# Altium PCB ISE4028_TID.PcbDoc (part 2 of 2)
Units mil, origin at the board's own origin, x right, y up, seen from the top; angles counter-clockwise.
Board outline 4000 x 3450 mil, 4 copper layers (Layer 1 - Top Layer, Layer 2 - GND, Layer 3 - PWR, Layer 4 - Bottom Layer), stack 61.434 mil thick; 151 components, 89 nets, 421 pads, 328 vias.
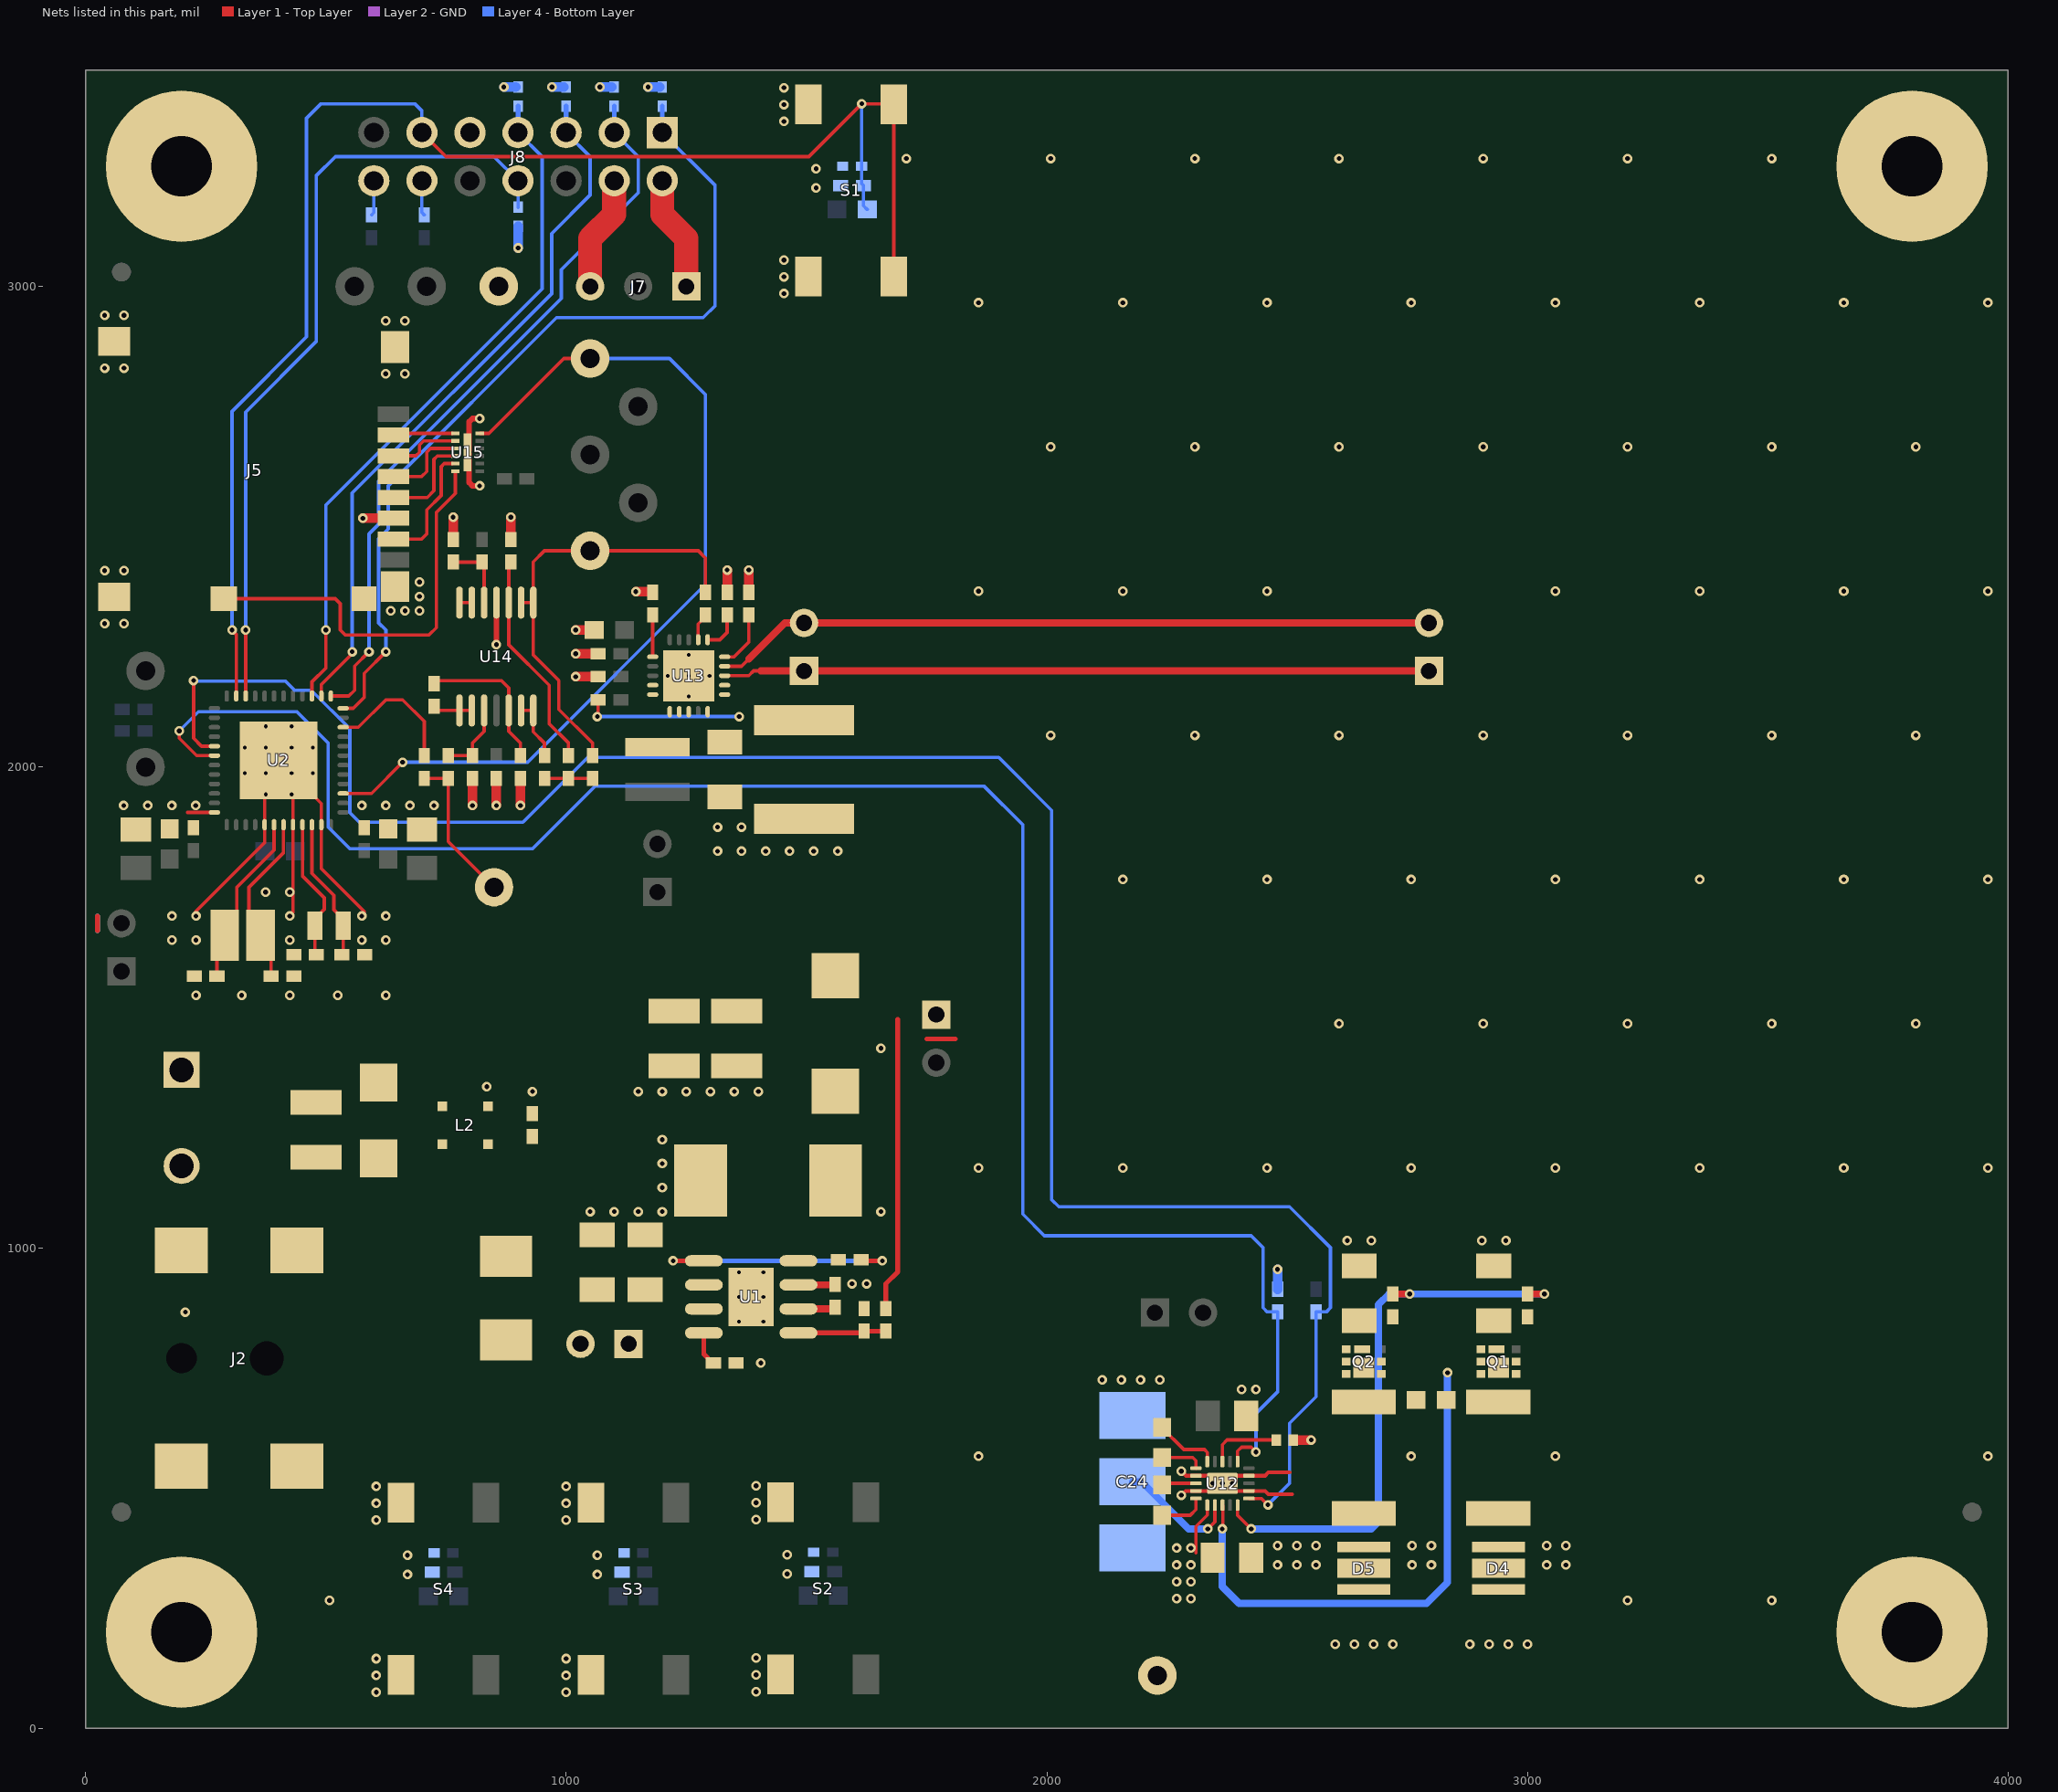
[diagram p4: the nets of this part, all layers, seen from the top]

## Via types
v1: diameter 20, hole 10, Layer 1 - Top Layer to Layer 4 - Bottom Layer, tented both sides, 305 vias
v2: diameter 19.68, hole 7.87, Layer 1 - Top Layer to Layer 4 - Bottom Layer, 17 vias
v3: diameter 19.68, hole 7.87, Layer 1 - Top Layer to Layer 4 - Bottom Layer, tented top, 6 vias

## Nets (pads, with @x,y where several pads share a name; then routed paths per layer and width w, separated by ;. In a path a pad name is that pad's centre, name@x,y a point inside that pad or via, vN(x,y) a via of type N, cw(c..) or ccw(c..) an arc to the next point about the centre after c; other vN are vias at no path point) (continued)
GND: C2.2 C3.2 C5.2 C6.2 C7.2 C8.2 C9.1 C10.1 C11.2 C12.1 C13.1 C14.2 C15.2 C16.2 C17.2 C18.2 C19.2 C20.2 C21.2 C22.2 C23.2 C24.2 C25.2 C28.2 C29.1 C30.2 C31.2 C32.2 C33.1 C35.2 C37.2 C38.2 D3.2 D6.1 H1.1 H2.1 H3.1 H4.1 J5.6 J5.9 J5.10 J5.12 J5.13 J5.14 J8.9 L2.3 R1.2 R3.1 R12.1 R20.1 R21.1 R26.1 R28.1 R29.1 R31.1 S1.3 S1.4 S2.3 S2.4 S3.3 S3.4 S4.3 S4.4 TP1.1 TP2.1 U1.7 U1.9 U2.36 U2.41 U2.44 U2.47 U2.49 U3.2 U4.2 U5.2 U6.2 U7.2 U8.2 U9.2 U10.2 U11.2 U12.7 U12.9 U12.17 U12.19 U12.21 U13.4 U13.5 U13.6 U13.21 U14.11 U15.13 | length 2699.3
  Layer 1 - Top Layer w7: 212.88,1905.71 U2.36@268.43,1905.71 ; v1@230,1695 230,1700 372.76,1842.76 U2.41@372.76,1880.12 372.76,1940.29 v2(375.58,1943.11) ; v2(429,1943.11) 431.82,1940.29 U2.44@431.82,1880.12 v1@431.82,1696.82 ; U2.49@470,1945 490.87,1924.13 U2.47@490.87,1880.12 490.87,1788.57 580,1699.44 v1@580,1695 ; U12.21@2349.62,493.98 v1(2365.37,509.72) ; U12.21@2349.62,525.47 v1(2365.37,509.72) ; U12.21@2381.12,493.98 v1(2365.37,509.72) ; U12.21@2381.12,525.47 v1(2365.37,509.72)
  Layer 1 - Top Layer w8: v1(2280,485) 2288.98,493.98 U12.19@2310.25,493.98 U12.21@2349.62,493.98 ; v1(2280,535) 2289.53,525.47 U12.17@2310.25,525.47 U12.21@2349.62,525.47 ; U12.21@2381.12,493.98 U12.7@2420.49,493.98 2454.02,493.98 2461,487 2510,487 ; U12.21@2381.12,525.47 U12.9@2420.49,525.47 2454.02,525.47 2461,532.45 2505,532.45
  Layer 1 - Top Layer w10: 25,1660 25,1690 ; 1750,1434.5 1810,1434.5
  Layer 1 - Top Layer w12: v1(820,2585) 805,2585 798.23,2591.77 798.23,2651.77 U15.13@795,2655 798.23,2658.23 798.23,2718.23 805,2725 v1(820,2725) ; v1(855,2255) U14.11@855,2342.2
  Layer 1 - Top Layer w15: U1.7@1483.39,922.73 1559.11,922.73 C8.2@1560,923.62
  Layer 1 - Top Layer w20: v1(577.36,2517.64) J5.6@640.75,2517.64 ; R31.1@765,2473.63 v1(765,2520) ; v1(805,1920) R29.1@805,1976.38 ; v1(855,1920) C28.2@855,1976.38 ; C31.2@885,2473.63 v1(885,2520) ; v1(905,1920) C32.2@905,1976.38 ; v1(1020,2187.98) R26.1@1066.38,2187.98 ; v1(1020,2235.96) C29.1@1066.38,2235.96 ; v1(1020,2285) C38.2@1058.5,2285 ; v1(1145,2365) 1178.62,2365 C33.1@1180,2363.62 ; C35.2@1335,2363.62 v1(1335,2410) ; R28.1@1380,2363.62 v1(1380,2410) ; D6.1@2515,600 v1(2550,600)
  Layer 2 - GND w10: 25,1660 25,1690
  Layer 4 - Bottom Layer w10: 25,1660 25,1690
  Layer 4 - Bottom Layer w20: v1(870.32,3414.69) U11.2@895,3414.69 ; v1(900,3080) U7.2@900,3125.31 ; v1(970.32,3414.69) U10.2@995,3414.69 ; v1(1070.32,3414.69) U8.2@1095,3414.69 ; v1(1170.32,3414.69) U6.2@1195,3414.69 ; R12.1@2480,913.62 v1(2480,955)
  other v1: 605,75 1000,75 1395,76.3 605,110 1000,110 1395,111.3 605,145 1000,145 1395,146.3 2600,175 2640,175 2680,175 2720,175 2880,175 2920,175 2960,175 3000,175 508,266 3208,266 3508,266 670,320 1065,320 1460,321.3 2480,340 2520,340 2560,340 2760,340 2800,340 3040,340 3080,340 670,360 1065,360 1460,361.3 2480,380 2520,380 2560,380 2760,380 2800,380 3040,380 3080,380 605,433.26 1000,433.27 1395,434.57 605,468.26 1000,468.27 1395,469.57 605,503.26 1000,503.27 1395,504.57 2345,510 2385.83,509.72 1858,566 2758,566 3058,566 3958,566 2405,705 2435,705 2115,725 2155,725 2195,725 2235,725 1405,760 208,866 1595,925 1625,925 2625,1015 2675,1015 2905,1015 2955,1015 1050,1075 1100,1075 1150,1075 1200,1075 1655,1075 1200,1125 1858,1166 2158,1166 2458,1166 2758,1166 3058,1166 3358,1166 3658,1166 3958,1166 1200,1175 1200,1225 930,1325 1150,1325 1200,1325 1250,1325 1300,1325 1350,1325 1400,1325 835,1335 1655,1415 2608,1466 2908,1466 3208,1466 3508,1466 3808,1466 230,1525 325,1525 425,1525 525,1525 625,1525 180,1640 230,1640 425,1640 575,1640 625,1640 180,1690 230,1690 425,1690 575,1690 625,1690 375,1740 425,1740 2158,1766 2458,1766 2758,1766 3058,1766 3358,1766 3658,1766 3958,1766 1315,1825 1365,1825 1415,1825 1465,1825 1515,1825 1565,1825 1315,1875 1365,1875 79.58,1920 129.58,1920 179.58,1920 229.58,1920 575,1920 625,1920 675,1920 725,1920 2008,2066 2308,2066 2608,2066 2908,2066 3208,2066 3508,2066 3808,2066 40,2298.5 80,2298.5 635,2325 665,2325 695,2325 695,2355 1858,2366 2158,2366 2458,2366 3058,2366 3358,2366 3658,2366 3958,2366 695,2385 40,2408.5 80,2408.5 2008,2666 2308,2666 2608,2666 2908,2666 3208,2666 3508,2666 3808,2666 624.65,2818.19 664.65,2818.19 40,2830 80,2830 624.65,2928.19 664.65,2928.19 40,2940 80,2940 1858,2966 2158,2966 2458,2966 2758,2966 3058,2966 3358,2966 3658,2966 3958,2966 1453.05,2985 1453.05,3020 1453.05,3055 1520,3205 1520,3245 1708,3266 2008,3266 2308,3266 2608,3266 2908,3266 3208,3266 3508,3266 1453.05,3343.27 1453.05,3378.27 1453.05,3413.27
  other v2: 331.42,1987.26 375.58,1987.26 429,1987.26 473.16,1987.26 331.42,2040.69 375.58,2040.69 429,2040.69 473.16,2040.69 375.58,2084.84 429,2084.84 1255,2146.69 1211.69,2190 1255,2190 1298.31,2190 1255,2233.31
  other v3: 1359.37,846.55 1410.55,846.55 1359.37,897.73 1410.55,897.73 1359.37,948.91 1410.55,948.91
HFXIN: C21.1 U2.42 Y2.1 | length 308.8
  Layer 1 - Top Layer w7: C21.1@273.62,1565 273.62,1634.02 Y2.1@289.6,1650 ; Y2.1@315,1695 315,1750 392.45,1827.45 U2.42@392.45,1880.12
HFXOUT: C22.1 U2.43 Y2.2 | length 314.1
  Layer 1 - Top Layer w7: Y2.2@340,1690 340,1750 412.13,1822.13 U2.43@412.13,1880.12 ; Y2.2@364.4,1650 386.38,1628.02 C22.1@386.38,1565
LFXIN: C17.1 U2.45 Y1.1 | length 273.2
  Layer 1 - Top Layer w7: U2.45@451.5,1880.12 451.5,1773.5 497,1728 497,1704 Y1.1@485,1692 ; Y1.1@477.47,1670 477.47,1613.15 C17.1@480.62,1610
LFXOUT: C18.1 U2.46 Y1.2 | length 272.5
  Layer 1 - Top Layer w7: U2.46@471.19,1880.12 471.19,1778.81 517,1733 517,1703 527,1693 Y1.2@528,1693 ; C18.1@533.38,1610 536.53,1613.15 Y1.2@536.53,1670
LM3550_FB: R18.1 R19.1 U12.5 | length 1208.1
  Layer 1 - Top Layer w7: U12.5@2396.87,464.45 2396.87,443.13 v1(2425,415)
  Layer 1 - Top Layer w15: R19.1@2720,903.62 v1(2755,903.62) ; R18.1@3000,903.62 v1(3035,903.62)
  Layer 4 - Bottom Layer w15: v1(2425,415) 2675,415 2690,430 2690,881.65 2711.97,903.62 v1(2755,903.62) v1(3035,903.62)
MSP_PWM: R27.1 R32.2 TP12.1 | length 315.7
  Layer 1 - Top Layer w7: R32.2@705,1976.38 R27.1@755,1976.38 755,1845 TP12.1@850,1750
MSP_PWM_FLT: C34.1 C36.2 TP11.1 U14.8 U14.9 | length 925.2
  Layer 1 - Top Layer w7: U14.9@906.18,2342.2 U14.8@931.77,2342.2 ; C34.1@1055,2023.63 1055,2050 985,2120 985,2180 931.77,2233.23 U14.8@931.77,2342.2 ; C36.2@1290,2363.62 1290,2435 1275,2450 TP11.1@1050,2450 955,2450 931.77,2426.77 U14.8@931.77,2342.2
NCS_SD: TP5.1 U2.3 U15.12 | length 1893.9
  Layer 1 - Top Layer w7: U2.3@536.15,1945.08 595.08,1945.08 v1(660,2010) ; U15.12@820.59,2694.37 839.37,2694.37 995,2850 TP5.1@1050,2850
  Layer 4 - Bottom Layer w7: v1(660,2010) 920,2010 1290,2380 1290,2775 1215,2850 TP5.1@1050,2850
NEOC: R9.1 U2.29 U12.6 | length 4359.2
  Layer 1 - Top Layer w7: v1(225,2180) 225,2060 241.5,2043.5 U2.29@268.43,2043.5 ; U12.6@2420.49,478.23 2446.77,478.23 v1(2460,465)
  Layer 4 - Bottom Layer w7: v1(225,2180) 226,2179 416,2179 435,2160 470,2160 550,2080 550,1905 570,1885 910,1885 1045,2020 1900,2020 2010,1910 2010,1100 2025,1085 2505,1085 2590,1000 2590,875 2581.38,866.38 R9.1@2560,866.38 2560,690 2505,635 2505,510 v1(2460,465)
NetC1_1: C1.1 D3.1 L1.1 U1.8
NetC1_2: C1.2 U1.1 | length 543.9
  Layer 1 - Top Layer w10: v1(1222.73,972.73) U1.1@1286.54,972.73 ; C1.2@1613.62,975 1615.89,972.73 v1(1657.73,972.73)
  Layer 4 - Bottom Layer w10: v1(1222.73,972.73) v1(1657.73,972.73)
NetC5_1: C5.1 D1.2 L2.2
NetC6_1: C6.1 C7.1 J1.1 L1.2 R2.2 | length 611.7
  Layer 1 - Top Layer w10: R2.2@1665,873.62 1665,925 1690,950 1690,1475
NetC8_1: C8.1 U1.6 | length 78.1
  Layer 1 - Top Layer w15: U1.6@1483.39,872.73 1556.35,872.73 C8.1@1560,876.38
NetC24_1: C24.1 C25.1 D4.1 D5.1 U12.1 | length 123.5
  Layer 1 - Top Layer w7: 2310,365 2310,420 2333.87,443.87 U12.1@2333.87,464.45 ; C25.1@2335,365 C25.1@2345,355
  other v1: 2270,270 2300,270 2270,305 2300,305 2270,340 2300,340 2270,375 2300,375
NetC24_3: C24.3 U12.2 | length 252.7
  Layer 1 - Top Layer w7: v1(2335,415) 2349.62,429.62 U12.2@2349.62,464.45
  Layer 4 - Bottom Layer w15: C24.3@2178.43,513.03 2196.97,513.03 2295,415 v1(2335,415)
NetC26_1: C26.1 U12.20 | length 92.8
  Layer 1 - Top Layer w7: C26.1@2245.37,443.23 2298.23,443.23 2310.25,455.25 U12.20@2310.25,478.23
NetC26_2: C26.2 U12.18 | length 71.6
  Layer 1 - Top Layer w7: C26.2@2240,506.5 2243.23,509.72 U12.18@2310.25,509.72
NetC27_1: C27.1 U12.15 | length 135.6
  Layer 1 - Top Layer w7: C27.1@2240,626.5 2240,625 2285,580 2328,580 2333.87,574.13 U12.15@2333.87,555
NetC27_2: C27.2 U12.16 | length 88.6
  Layer 1 - Top Layer w7: C27.2@2240,563.5 2303.5,563.5 2310.25,556.75 U12.16@2310.25,541.22
NetC30_1: C30.1 C37.1 R22.2 U13.10 U13.11 U13.12 | length 330
  Layer 1 - Top Layer w7: v1@1066.38,2105 R22.2@1066.38,2140
  Layer 4 - Bottom Layer w7: v1(1065,2105) v1(1360,2105)
NetC31_1: C31.1 R24.2 U14.10 | length 456.1
  Layer 1 - Top Layer w7: C31.1@885,2426.38 880.59,2421.98 U14.10@880.59,2342.2 880.59,2254.41 965,2170 965,2090 1005,2050 R24.2@1005,2023.63
NetC32_1: C32.1 R25.2 U14.5 | length 315.6
  Layer 1 - Top Layer w7: R25.2@725,2173.62 731.38,2180 865,2180 880.59,2164.41 U14.5@880.59,2117.8 880.59,2074.41 905,2050 C32.1@905,2023.63
NetC33_2: C33.2 U13.1 | length 87.1
  Layer 1 - Top Layer w7: C33.2@1180,2316.38 1180.2,2316.18 U13.1@1180.2,2229.37
NetC34_2: C34.2 R23.2 R24.1 | length 100
  Layer 1 - Top Layer w7: R23.2@960,1976.38 C34.2@1060,1976.38
NetC35_1: C35.1 U13.16 | length 83.3
  Layer 1 - Top Layer w7: U13.16@1294.37,2264.8 1319.8,2264.8 1335,2280 C35.1@1335,2316.38
NetC36_1: C36.1 U13.17 | length 44.6
  Layer 1 - Top Layer w7: U13.17@1274.68,2264.8 1274.68,2297.68 C36.1@1283,2306
NetD1_1: D1.1 J3.2
NetD4_2: D4.2 D4.3 R15.2
NetD5_2: D5.2 D5.3 R16.2
NetD6_2: D6.2 U12.13 | length 151.3
  Layer 1 - Top Layer w7: U12.13@2365.37,555 2365.37,590.37 2375,600 D6.2@2477.28,600
NetJ5_2: J5.2 U15.1 | length 125.1
  Layer 1 - Top Layer w7: J5.2@640.75,2690.87 644.25,2694.37 U15.1@764.41,2694.37
NetJ5_3: J5.3 U15.2 | length 145.3
  Layer 1 - Top Layer w7: J5.3@640.75,2647.56 687.56,2647.56 695,2655 695,2670 703.62,2678.62 U15.2@764.41,2678.62
NetJ5_4: J5.4 U15.3 | length 171.4
  Layer 1 - Top Layer w7: J5.4@640.75,2604.25 699.25,2604.25 710,2615 710,2655 717.87,2662.87 U15.3@764.41,2662.87
NetJ5_5: J5.5 U15.4 | length 197.4
  Layer 1 - Top Layer w7: J5.5@640.75,2560.94 710.94,2560.94 725,2575 725,2640 732.13,2647.13 U15.4@764.41,2647.13
NetJ5_7: J5.7 U15.5 | length 253.1
  Layer 1 - Top Layer w7: J5.7@640.75,2474.33 699.33,2474.33 710,2485 710,2535 740,2565 740,2625 746.38,2631.38 U15.5@764.41,2631.38
NetJ5_11: J5.11 U15.6 | length 853.5
  Layer 1 - Top Layer w7: J5.11@287.99,2350.12 519.88,2350.12 530,2340 530,2285 540,2275 715,2275 730,2290 730,2530 769.41,2569.41 U15.6@769.41,2615.63
NetJ8_12: J8.12 R13.2 | length 73.4
  Layer 4 - Bottom Layer w7: J8.12@700,3220 700,3153.62 R13.2@705,3148.62
NetJ8_14: J8.14 R14.2 | length 73.4
  Layer 4 - Bottom Layer w7: R14.2@595,3148.62 600,3153.62 J8.14@600,3220
NetJ11_1: J11.1 LS1.1 U13.13 | length 1469.3
  Layer 1 - Top Layer w7: U13.13@1329.8,2190 1380,2190 1390,2200 1405,2200
  Layer 1 - Top Layer w15: 1405,2200 J11.1@1495,2200 LS1.1@2795,2200
NetJ11_2: J11.2 LS1.2 U13.14 | length 1502.6
  Layer 1 - Top Layer w7: U13.14@1329.8,2209.68 1364.68,2209.68 1380,2225
  Layer 1 - Top Layer w15: 1380,2225 1455,2300 J11.2@1495,2300 LS1.2@2795,2300
NetL4_1: L4.1 U13.7 U13.8
NetQ1_1: Q1.1 Q1.2 Q1.5 Q1.6 Q1.8 R15.1 R17.1 U12.3 | length 1107.8
  Layer 1 - Top Layer w7: v1(2365,415) 2366.18,416.18 2366.18,463.64 U12.3@2365.37,464.45
  Layer 4 - Bottom Layer w15: v1(2365,415) 2365,295 2400,260 2790,260 2833.62,303.62 v1(2833.62,740)
NetQ1_4: Q1.4 Q1.7 R18.2 R20.2
NetQ2_1: Q2.1 Q2.2 Q2.5 Q2.6 Q2.8 R16.1 R17.2
NetQ2_4: Q2.4 Q2.7 R19.2 R21.2
NetR1_1: R1.1 U1.4 | length 71.8
  Layer 1 - Top Layer w10: U1.4@1286.54,822.73 1286.54,778.46 1305,760 R1.1@1306.38,760
NetR2_1: R2.1 R3.2 U1.5 | length 178.1
  Layer 1 - Top Layer w10: U1.5@1483.39,822.73 1611.35,822.73 1615,826.38 R3.2@1620,826.38 R2.1@1660,826.38
NetR23_1: R23.1 U14.6 U14.7 | length 129.4
  Layer 1 - Top Layer w7: U14.6@906.18,2117.8 U14.7@931.77,2117.8 931.77,2073.23 955,2050 R23.1@955,2023.63
NetR25_1: R25.1 U14.1 U14.2 | length 82.4
  Layer 1 - Top Layer w7: R25.1@725,2126.38 733.58,2117.8 U14.1@778.23,2117.8 U14.2@803.82,2117.8
NetR27_2: R27.2 R29.2 U14.3 | length 154.3
  Layer 1 - Top Layer w7: R27.2@755,2023.63 R29.2@805,2023.63 805,2050 829.41,2074.42 U14.3@829.41,2117.8
NetR28_2: R28.2 U13.15 | length 119.3
  Layer 1 - Top Layer w7: U13.15@1329.8,2229.37 1349.37,2229.37 1380,2260 R28.2@1380,2316.38
NetR30_1: R30.1 R31.2 U14.12 | length 146
  Layer 1 - Top Layer w7: R31.2@765,2426.38 R30.1@825,2426.38 829.41,2421.97 U14.12@829.41,2342.2
NetR32_1: R32.1 U2.10 | length 282.5
  Layer 1 - Top Layer w7: U2.10@536.15,2082.87 567.87,2082.87 625,2140 660,2140 705,2095 R32.1@705,2023.62
NetU14_13: U14.13 U14.14 | length 25.6
  Layer 1 - Top Layer w7: U14.14@778.23,2342.2 U14.13@803.82,2342.2
NRST: C15.1 J8.11 R6.1 S1.1 S1.2 U2.23 U9.1 | length 3205.2
  Layer 1 - Top Layer w7: v1(305,2285) 313.71,2276.29 U2.23@313.71,2147.83 ; J8.11@700,3320 750,3270 1505,3270 v1(1615,3380) 1680.77,3380 S1.1@1681.63,3379.13 S1.2@1681.63,3020.87
  Layer 4 - Bottom Layer w7: v1(305,2285) 305,2740 460,2895 460,3350 490,3380 685,3380 700,3365 J8.11@700,3320 ; v1(1615,3380) 1615,3250.31 U9.1@1614.68,3250 1614.68,3213.94 C15.1@1618.62,3210 1618.62,3167.87 R6.1@1626.5,3160
STROBE: R12.2 U2.30 U12.11 | length 4057.6
  Layer 1 - Top Layer w7: v1(195,2075) 195,2060 231.18,2023.82 U2.30@268.43,2023.82 ; U12.11@2396.87,555 2396.87,576.87 2405,585 2425,585 v1(2435,575)
  Layer 4 - Bottom Layer w7: v1(195,2075) 235,2115 440,2115 505,2050 505,1875 550,1830 930,1830 1060,1960 1870,1960 1950,1880 1950,1070 1995,1025 2425,1025 2450,1000 2450,875 2458.62,866.38 R12.2@2480,866.38 2480,700 2435,655 v1(2435,575)
TCK: J8.7 U2.15 U11.1 | length 1446.5
  Layer 1 - Top Layer w7: U2.15@471.19,2147.83 471.19,2177.19 500,2206 v1(500,2285)
  Layer 4 - Bottom Layer w7: v1(500,2285) 500,2545 950,2995 950,3270 J8.7@900,3320
  Layer 4 - Bottom Layer w10: J8.7@900,3320 U11.1@900,3375.31
TDI: J8.3 U2.13 U8.1 | length 1534.9
  Layer 1 - Top Layer w7: U2.13@510.56,2147.83 547.83,2147.83 560,2160 560,2210 v1(590,2240)
  Layer 4 - Bottom Layer w7: v1(590,2240) 590,2485 610,2505 610,2595 990,2975 990,3035 1150,3195 1150,3270 J8.3@1100,3320
  Layer 4 - Bottom Layer w10: J8.3@1100,3320 U8.1@1100,3375.31
TDO: J8.1 U2.12 U6.1 | length 1822.6
  Layer 1 - Top Layer w7: U2.12@536.15,2122.24 557.24,2122.24 580,2145 580,2195 v1(625,2240)
  Layer 4 - Bottom Layer w7: v1(625,2240) 625,2285 610,2300 610,2475 630,2495 630,2585 980,2935 1285,2935 1310,2960 1310,3210 J8.1@1200,3320
  Layer 4 - Bottom Layer w10: J8.1@1200,3320 U6.1@1200,3375.31
TEST: J8.8 U2.22 U7.1 | length 1655.5
  Layer 1 - Top Layer w7: U2.22@333.39,2147.83 v1(333.39,2285)
  Layer 4 - Bottom Layer w7: v1(333.39,2285) 333.39,2738.39 480,2885 480,3230 520,3270 850,3270 J8.8@900,3220 U7.1@900,3164.69
TMS: J8.5 U2.14 U10.1 | length 1479.8
  Layer 1 - Top Layer w7: U2.14@490.87,2147.83 490.87,2171.87 555,2236 v1(555,2240)
  Layer 4 - Bottom Layer w7: v1(555,2240) 555,2570 970,2985 970,3110 1050,3190 1050,3270 J8.5@1000,3320
  Layer 4 - Bottom Layer w10: J8.5@1000,3320 U10.1@1000,3375.31
VCC_TARGET: J7.3 J8.4 | length 240.7
  Layer 1 - Top Layer w50: J7.3@1050,3000 1050,3100 1100,3150 J8.4@1100,3220
VCC_TOOL: J7.1 J8.2 | length 240.7
  Layer 1 - Top Layer w50: J8.2@1200,3220 1200,3150 1250,3100 J7.1@1250,3000
VIN: C4.2 D2.2 J2.1 J2.1A J4.2 L2.1
VIN_FLT: C2.1 C3.1 J3.1 U1.2 U1.3
VIN_GND: C4.1 D2.1 J2.2 J2.3 J4.1 L2.4
pads on no net: FID1.1 FID2.1 FID3.1 FID4.1 FID5.1 FID6.1 J2.MH1 J2.MH2 J5.1 J5.8 J8.6 J8.10 J8.13 U2.1 U2.2 U2.7 U2.8 U2.19 U2.26 U2.27 U2.28 U2.33 U2.34 U2.35 U2.38 U2.39 U2.40 U12.12 U13.9

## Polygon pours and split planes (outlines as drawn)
DVCC on Layer 3 - PWR "Layer 3 - PWR- DVCC" (solid, remove dead copper, pour order 18): 40,1645 90,1645 175,1730 310,1730 355,1775 720,1775 775,1830 775,2465 745,2495 735,2505 735,2565 735,2580 770,2615 870,2615 910,2575 910,2410 940,2380 1100,2380 1170,2450 1495,2450 1530,2485 1530,3170 420,3170 200,2950 115,2865 115,2545 115,2300 50,2235 40,2225
3V3 on Layer 3 - PWR "Layer 3 - PWR- 3V3" (solid, remove dead copper, pour order 15): 40,1610 835,1610 925,1700 1000,1775 1195,1775 1910,1775 2270,1415 2270,830 2220,780 1780,780 1650,650 110,650 40,720
3V3_PIEZO on Layer 3 - PWR "Layer 3 - PWR- 3V3_PIEZO" (solid, remove dead copper, pour order 17): 805,2530 805,2080 845,2040 1030,2040 1055,2015 1055,1830 1080,1805 1190,1805 1235,1805 1260,1830 1260,2075 1180,2155 1180,2290 1120,2350 930,2350 855,2425 855,2530 845,2540 815,2540
GND on Layer 3 - PWR "Layer 3 - PWR- GND" (solid, remove dead copper, pour order 19): 20,20 3980,20 3980,3430 20,3430
GND on Layer 2 - GND "Layer 2 - GND- GND" (solid, remove dead copper, pour order 14): 20,20 3980,20 3980,3430 20,3430
GND on Layer 1 - Top Layer "Layer 1 - Top Layer- GND" (solid, remove dead copper, pour order 13): 20,20 3980,20 3980,3430 20,3430
GND on Layer 4 - Bottom Layer "Layer 4 - Bottom Layer- GND" (solid, remove dead copper, pour order 22): 20,20 3980,20 3980,3430 20,3430

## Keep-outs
Keep-Out Layer:
  lines w20: -10,0 ccw(c0,0) 0,-10 4000,-10 ccw(c4000,0) 4010,0 4010,3450 ccw(c4000,3450) 4000,3460 0,3460 ccw(c0,3450) -10,3450 -10,0
  text ".Layer_Name" at 577,-858.49 h60

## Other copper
Layer 1 - Top Layer:
  pour cut-out: 550,3370 750,3370 750,3285 850,3285 850,3370 1250,3370 1250,3170 550,3170
  pour cut-out: 780,1235 810,1235 810,1345 780,1375
  pour cut-out: 593,2534 593,2407 712,2407 712,2534
  pour cut-out: 1510,1390 1495,1390 1432,1327 1432,1311
  pour cut-out: 2390,315 2395,315 2395,390 2450,390 2450,445 2390,445
  pour cut-out: 1650,835 1330,835 1330,960 1650,960
  pour cut-out: 1105,2010 1605,2010 1620,2010 1620,1970 1605,1970 1605,1910 1105,1910
  pour cut-out: 895,2730 895,2680 1030,2545 1205,2545 1205,2750 915,2750
  pour cut-out: 1050,2955 1230,2955 1230,3140 1165,3205 1115,3205 1050,3140
  pour cut-out: 615,2135 935,2135 935,2285 900,2320 710,2320 615,2225
  pour cut-out: 70,1840 70,1785 140,1715 480,1715 480,1965 355,1965 240,1965 240,1840
  pour cut-out: 550,1855 555,1850 740,1850 740,1990 605,1990 555,1940
  pour cut-out: 300,1900 525,1900 525,2125 300,2125
  region net 3V3_PIEZO: 1120,1970 1120,1830 1140,1810 1240,1810 1260,1830 1260,1970
  region net NetL4_1: 1260,2127 1260,2020 1120,2020 1120,2075 1130,2085 1219,2085 1230,2096 1230,2127
  region net NetC30_1: 1289,2127 1313,2127 1318,2132 1318,2175 1415,2175 1440,2150 1605,2150 1605,2020 1289,2020
  region net GND: 1168,2175 1198,2175 1202,2179 1211,2179 1225,2165 1225,2137 1221,2133 1221,2100 1178,2100 1168,2110
  region net GND: 810,1260 810,1365 860,1415 1432,1415 1432,953 1445,940 1625,940 1635,930 1635,855 1600,855 1590,865 1590,895 1580,905 1445,905 1432,892 1432,762 1415,745 1337,745 1337,993 1330,1000 1000,1000 970,1030 970,1250 960,1260
  region net GND: 2890,935 2970,935 2970,1030 2890,1030
  region net GND: 2610,935 2690,935 2690,1030 2610,1030
  region net GND: 2395,390 2490,390 2490,315 2400,315 2395,320
  region net GND: 2390,615 2450,615 2450,720 2390,720
  region net GND: 550,2398 559,2407 710,2407 710,2310 695,2295 550,2295
  region net GND: 20,2283.5 100,2283.5 100,2423.5 20,2423.5
  region net GND: 604.65,2803.19 684.65,2803.19 684.65,2943.19 604.65,2943.19
  region net GND: 20,2815 100,2815 100,2955 20,2955
  region net GND: 685,65 590,65 590,155 685,155
  region net GND: 685,423.26 590,423.26 590,513.26 685,513.26
  region net GND: 1080,65 985,65 985,155 1080,155
  region net GND: 1080,423.27 985,423.27 985,513.27 1080,513.27
  region net GND: 1475,424.57 1380,424.57 1380,514.57 1475,514.57
  region net GND: 1475,66.3 1380,66.3 1380,156.3 1475,156.3
  region net NetC24_1: 2375,390 2375,310 2385,300 3015,300 3015,230 2985,200 2325,200 2250,275 2250,390
  region net 3V3_LED: 2365,615 2365,875 2345,895 2305,895 2285,875 2285,635 2305,615
  region net NetQ1_4: 2890,780 2890,875 3015,875 3015,835 3000,820 2965,820 2955,810 2955,780
  region net NetQ2_4: 2610,780 2610,875 2735,875 2735,835 2720,820 2685,820 2675,810 2675,780
  region net NetQ1_1: 3013.9,645 2808.9,645 2808.9,741 2838.9,771 3013.9,771
  region net NetQ2_1: 2585,645 2790,645 2790,741 2760,771 2610,771 2585,746
  region net NetD4_2: 2865,480 2865,310 3015,310 3015,480
  region net NetD5_2: 2585,480 2585,310 2735,310 2735,480
  region net NetC5_1: 950,930 950,1240 940,1250 810,1250 810,930
  region net VIN_GND: 770,1272 168.62,1272 95,1187.86 95,685 175,605 505,605 505,490 125,490 75.31,539.69 65.27,549.73 20,595 20,1295 140,1415 720,1415 770,1365
  region net VIN: 140,940 140,1165 205,1230 685,1230 693,1238 770,1238 770,1230 770,1120 590,940
  region net NetC6_1: 1170,1455 1800,1455 1800,1525 1710,1615 1260,1615 1170,1525
  region net NetC1_1: 1444,960 1585,960 1585,1010 1620,1045 1620,1375 1513,1375 1444,1306
  region net NetD1_1: 1060,765 810,765 810,855 1020,855 1060,815
  region net VIN_FLT: 1326,940 1025,940 1025,885 1085,825 1085,765 1205,765 1230,790 1230,845 1245,860 1326,860
  region net GND: 570,1855 600,1855 610,1845 735,1845 735,1930 565,1930 565,1860
  region net AVCC: 505,1892 518,1892 567,1843 596,1843 610,1829 735,1829 735,1735 730,1730 570,1730 505,1795
  region net DVCC: 299.58,1892 286.58,1892 237.58,1843 208.58,1843 194.58,1829 69.58,1829 69.58,1735 74.58,1730 235,1730 299.58,1794.58
  region net GND: 234.58,1855 204.58,1855 194.58,1845 69.58,1845 69.58,1930 239.58,1930 239.58,1860
  region net GND: 245,1715 245,1545 255,1535 405,1535 415,1545 415,1710 400,1725 360,1725 360,1740 430,1810 435,1810 435,1760 450,1745 450,1590 465,1575 550,1575 565,1590 565,1715 625,1715 640,1700 640,1525 625,1510 165,1510 150,1525 150,1695 150,1705 160,1715
  region net GND: 1290,1970 1290,1830 1310,1810 1585,1810 1605,1830 1605,1970
  region net GND: 1533.05,2975 1438.05,2975 1438.05,3065 1533.05,3065
  region net GND: 1533.05,3333.27 1438.05,3333.27 1438.05,3423.27 1533.05,3423.27
  pour cut-out: 1405,2145 2695,2145 2715,2125 2845,2125 2865,2145 2865,2355 2845,2375 2715,2375 2695,2355 1570,2355 1550,2375 1435,2375 1405,2345
  pour cut-out: 110,925 130,925 130,930 110,930
  text ".Layer_Name" at 577,-858.49 h60
Layer 2 - GND:
  pour cut-out: 550,3370 750,3370 750,3285 850,3285 850,3370 1250,3370 1250,3170 550,3170
  pour cut-out: 1420,2120 1570,2120 1570,2375 1420,2375
  pour cut-out: 2720,2125 2870,2125 2870,2375 2720,2375
  text ".Layer_Name" at 577,-858.49 h60
Layer 3 - PWR:
  pour cut-out: 380,1955 345,1990 345,2040 380,2075 425,2075 460,2040 460,1990 425,1955
  pour cut-out: 550,3370 750,3370 750,3285 850,3285 850,3370 1250,3370 1250,3170 550,3170
  pour cut-out: 2720,2125 2870,2125 2870,2375 2720,2375
  pour cut-out: 1420,2120 1570,2120 1570,2375 1420,2375
  text ".Layer_Name" at 577,-858.49 h60
Layer 4 - Bottom Layer:
  pour cut-out: 2035,1100 2120,1100 2120,1135 2035,1135
  pour cut-out: 2390,245 2320,245 2320,380 2390,380
  pour cut-out: 550,3370 750,3370 750,3285 850,3285 850,3370 1250,3370 1250,3170 550,3170
  region net GND: 2100,595 2255,595 2255,740 2100,740
  region net GND: 740,310 655,310 655,365 665,375 740,375
  region net GND: 1135,310 1050,310 1050,365 1060,375 1135,375
  region net GND: 1530,311.3 1445,311.3 1445,366.3 1455,376.3 1530,376.3
  region net NetC24_1: 2105,430 2245,430 2285,390 2315,390 2315,260 2170,260 2105,325
  region net DVCC: 395,1845 395,1805 290,1805 275,1820 275,1830 290,1845
  region net AVCC: 415,1805 515,1805 530,1820 530,1830 515,1845 415,1845
  region net GND: 1590,3195 1505,3195 1505,3250 1515,3260 1590,3260
  pour cut-out: 2720,2125 2870,2125 2870,2375 2720,2375
  pour cut-out: 1420,2120 1570,2120 1570,2375 1420,2375
  text ".Layer_Name" at 577,-858.49 h60

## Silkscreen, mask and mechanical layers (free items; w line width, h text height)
Top Overlay:
  circle w10: c2795,2250 r1181.1
  text "RST" at 1560,2940 h40
  text ".TID" at 3290,600 h100
  text "BTN_LED" at 655,550 h40
  text "BTN_GAIN" at 1040,550 h40
  text "BTN_AUDIO" at 1435,549.65 h40
  text ".PRJ_Number" at 3300,500 h100
  text ".PCB_Rev" at 3680,500 h100
  text "8-30V" at 150,430 h80
  text "2A" at 150,370 h80
  text ".Layer_Name" at 577,-858.49 h60
Bottom Overlay:
  text ".Layer_Name" at 577,-858.49 h60
Top Paste:
  text ".Layer_Name" at 577,-858.49 h60
Bottom Paste:
  text ".Layer_Name" at 577,-858.49 h60
Top Solder:
  text ".Layer_Name" at 577,-858.49 h60
  text ".Layer_Name" at 577,-858.49 h60
Bottom Solder:
  text ".Layer_Name" at 577,-858.49 h60
Drill Guide:
  text ".Layer_Name" at 577,-858.49 h60
M1 Board Outline:
  the board outline again, w10
  text ".Layer_Name" at 577,-858.49 h60
M2 Board Dimensions:
  rectangle: 0,-275 125,-150
  rectangle: 125,-400 500,-275
  lines w7: 0,-275 1000,-275 ; 125,-400 125,-150 ; 250,-400 250,-150 ; 500,-400 500,-150 ; 750,-400 750,-150 ; 0,-400 1000,-400 1000,-150 0,-150 0,-400
  text ".Layer_Name" at 577,-858.49 h60
M3 3D STEP Top:
  text ".Layer_Name" at 577,-858.49 h60
M4 3D STEP Bottom:
  text ".Layer_Name" at 577,-858.49 h60
M5 Assembly Top:
  lines w10: -292,-930.17 6308,-930.17 ; -292,-726.83 6310,-726.83 ; -292,-523.5 -292,-1133.5 3713,-1133.5 6310,-1133.5 6310,-523.5 -291.5,-523.5 -291.5,-1133.5 1284,-1133.5 ; 2173,-1133.5 2173,-523.5 ; 3440,-726.83 3440,-523.5 ; 4280,-726.83 4280,-523.5 ; 4902,-1140 4902,-937.17
  text "COMPONENTS MARKED 'DNP' SHOULD NOT BE POPULATED." at 1153.5,-318.5 h60
  text "ASSEMBLY VARIANT:" at 1153,-434 h60
  text ".VariantName" at 2189,-434 h60
  text "PCB VIEWED FROM TOP SIDE" at -228.5,-655.67 h60
  text "BOARD #:" at 2248,-655.67 h60
  text ".PRJ_Number" at 2793.5,-655.67 h60
  text "REV:" at 3638,-655.67 h60
  text ".PCB_Rev" at 3929.5,-655.67 h60
  text "SVN REV:" at 4476,-655.67 h60
  text ".VersionControl_RevNumber" at 4982,-655.67 h60
  text "TID #:" at 2248,-859 h60
  text ".TID" at 2793.5,-859 h60
  text "PLOT NAME =" at -228.5,-1064.34 h60
  text ".plot_File_Name" at 577,-1064.34 h60
  text "GENERATED    :" at 2250,-1064.34 h60
  text ".Print_Date" at 3119.5,-1064.34 h60
  text ".Print_Time" at 3848.5,-1064.34 h60
  text "TEXAS INSTRUMENTS" at 5113,-1064.34 h60
M6 Assembly Bottom:
  lines w10: -292.5,-727.33 6309.5,-727.33 ; -290.5,-930.67 6309.5,-930.67 ; 1115.5,-1140.5 1115.5,-937.67 ; 1737.5,-727.33 1737.5,-524 ; 2577.5,-727.33 2577.5,-524 ; 3844.5,-1134 3844.5,-524 ; 4733.5,-1134 6309,-1134 6309,-524 -292.5,-524 -292.5,-1134 2304.5,-1134 6309.5,-1134 6309.5,-524
  text "COMPONENTS MARKED 'DNP' SHOULD NOT BE POPULATED." at 6102,-318 h60
  text ".VariantName" at 5058,-434 h60
  text "ASSEMBLY VARIANT:" at 6097,-434 h60
  text ".VersionControl_RevNumber" at 1035.5,-656.17 h60
  text "SVN REV:" at 1541.5,-656.17 h60
  text ".PCB_Rev" at 2088,-656.17 h60
  text "REV:" at 2379.5,-656.17 h60
  text ".PRJ_Number" at 3224,-656.17 h60
  text "BOARD #:" at 3769.5,-656.17 h60
  text "PCB VIEWED FROM BOTTOM SIDE" at 6246,-656.17 h60
  text ".TID" at 3224,-859.5 h60
  text "TID #:" at 3769.5,-859.5 h60
  text "TEXAS INSTRUMENTS" at 904.5,-1064.84 h60
  text ".Print_Time" at 2169,-1064.84 h60
  text ".Print_Date" at 2898,-1064.84 h60
  text "GENERATED    :" at 3767.5,-1064.84 h60
  text ".plot_File_Name" at 5440.5,-1064.84 h60
  text "PLOT NAME =" at 6246,-1064.84 h60
M9 Title Sheet:
  drawing of 1178 lines, arcs and shapes, not listed
  text "1" at 739.84,8036.5 h70
  text "2" at 3235.5,8036.5 h70
  text "3" at 5724.84,8036.5 h70
  text "4" at 8231.51,8036.5 h70
  text "5" at 10730.5,8036.5 h70
  text "6" at 13235.5,8036.5 h70
  text "A" at -416.5,6893.5 h70
  text "A" at 14383.5,6893.5 h70
  text "B" at -416.5,4513.5 h70
  text "B" at 14383.5,4513.5 h70
  text "C" at -416.5,2138.5 h70
  text "C" at 14383.5,2138.5 h70
  text "PROJECT TITLE:" at 11343.5,277.5 h45
  text ".PRJ_Title" at 11393.5,144.17 h70
  text "DESIGNED FOR:" at 11343.5,-23.5 h45
  text ".PRJ_Customer" at 11393.5,-163.5 h70
  text "D" at -416.5,-231.5 h70
  text "D" at 14383.5,-231.5 h70
  text "FILE NAME:" at 11343.5,-323.5 h45
  text ".PCB_File_Name_No_Path" at 11393.5,-443.5 h70
  text "Texas Instruments (TI) and/or its licensors do not warrant the accuracy or completeness of this specification" at 6374,-605.34 h45
  text "ENGINEER:" at 11343.5,-613.5 h45
  text "LAYOUT BY:" at 12848.5,-613.5 h45
  text "or any information contained therein. TI and/or its licensors do not warrant that this design will meet" at 6329.01,-718 h45
  text ".PRJ_Engineer" at 11393.5,-768.49 h70
  text ".PCB_Layout" at 12899,-768.49 h70
  text "JMM" at 12851,-801 h100
  text "s  o  l  u  t  i  o  n  s" at 13709,-804 h68
  text "the specifications, will be suitable for your application or fit for any particular purpose, or will operate in" at 6329.01,-830.67 h45
  text ".Layer_Name" at 577,-858.49 h60
  text "ALTIUM DESIGNER VERSION:" at 12848.5,-923.5 h45
  text "an implementation. TI and/or its licensors do not warrant that the design is production worthy. You should" at 6329.01,-943.33 h45
  text "completely validate and test your design implementation to confirm the system functionality for your application." at 6374,-1056 h45
  text ".print_Scale" at 11393.5,-1056.83 h70
  text ".Application_BuildNumber" at 12899,-1056.83 h70
  text "1" at 739.84,-1263.5 h70
  text "2" at 3235.5,-1263.5 h70
  text "3" at 5724.84,-1263.5 h70
  text "4" at 8231.51,-1263.5 h70
  text "5" at 10730.5,-1263.5 h70
  text "6" at 13235.5,-1263.5 h70
M10 Fab Notes:
  drawing of 185 lines, arcs and shapes, not listed
  text "DESIGN INFORMATION" at 12381.02,5910 h60
  text "MIN. TRACK WIDTH:" at 11736.46,5730 h60
  text "8" at 12832.7,5730 h60
  text "MIL" at 12987.46,5730 h60
  text "MIN. CLEARANCE:" at 11736.46,5598 h60
  text "0.2" at 12772.7,5598 h60
  text "mm" at 12987.46,5598 h60
  text "MIN. VIA PAD SIZE:" at 11736.46,5466 h60
  text "20" at 12802.71,5466 h60
  text "MIL" at 12987.46,5466 h60
  text "0.05mm (2MIL)" at 12431.46,5324.29 h60
  text "MINIMUM ANNULAR RING" at 11407.23,5320 h60
  text "EXTERNAL" at 13139.46,5320 h60
  text "PER" at 11607.23,5202 h60
  text "IPC-D-275 CLASS 2 LEVEL C" at 11827.23,5202 h60
  text "MIL, HOLES" at 13315.46,5089.71 h60
  text "+/-" at 12923,5089 h60
  text "+/-" at 13777,5089 h60
  text "REGISTRATION TOLERANCES:" at 11407.23,5084 h60
  text "METAL" at 12607,5084 h60
  text "5" at 13183.2,5084 h60
  text "3" at 14016.2,5084 h60
  text "MIL" at 14132.46,5084 h60
  text "MATERIAL:" at 11332.46,4874.54 h60
  text "FR-4 High Tg" at 12318.9,4734.21 h60
  text "FR-408" at 11753.46,4725.64 h60
  text "X" at 12165.46,4725.64 h60
  text "OTHER" at 13241.46,4725.64 h60
  text "62 MIL (1.6mm) +/-10%" at 12073.56,4562.92 h60
  text "THICKNESS:" at 11407.23,4558.64 h60
  text "X" at 11945.4,4558.64 h60
  text "OTHER" at 13358.46,4558.64 h60
  text "TOLERANCE:" at 11407.23,4400.64 h60
  text "X" at 12246.53,4400.64 h60
  text "ANSI IPC-6012 TYPE 3 CLASS 2" at 12433.48,4400.64 h60
  text "OTHER +/-" at 12433.46,4244.64 h60
  text "BOW & TWIST:" at 11407.23,4087.64 h60
  text "X" at 12246.53,4087.64 h60
  text "ANSI IPC-6012 TYPE 3 CLASS 2" at 12433.48,4087.64 h60
  text "OTHER +/-" at 12433.46,3929.13 h60
  text "DRILLING:" at 11332.46,3790.64 h60
  text "REFERENCE:" at 11407.23,3673.64 h60
  text "X" at 12055.46,3673.64 h60
  text "AS SHOWN" at 12242.46,3673.64 h60
  text "X" at 12956.46,3673.64 h60
  text "NC_DRILL FILES" at 13093.46,3673.64 h60
  text "PTH MIN COPPER THICKNESS:" at 11407.23,3515.64 h60
  text "X" at 12757.46,3515.64 h60
  text "1MIL" at 12894.46,3515.64 h60
  text "OTHER" at 13391.46,3515.64 h60
  text "BOARD FINISH:" at 11332.46,3356.64 h60
  text "SILKSCREEN:" at 11487.68,3238.64 h60
  text "X" at 12436.46,3238.64 h60
  text "TOP" at 12562.46,3238.64 h60
  text "X" at 12946.46,3238.64 h60
  text "BOTTOM" at 13073.46,3238.64 h60
  text "SILKSCREEN COLOR:" at 11487.68,3071.64 h60
  text "X" at 12435.42,3071.64 h60
  text "WHITE" at 12562.46,3071.64 h60
  text "OTHER" at 13073.46,3071.64 h60
  text "SOLDER RESIST COLOR:" at 11487.68,2901.64 h60
  text "X" at 12055.42,2742.44 h60
  text "GREEN" at 12182.46,2742.44 h60
  text "BLUE" at 12773.46,2742.44 h60
  text "OTHER" at 13311.46,2742.44 h60
  text "IMMERSION GOLD (ENIG)" at 12393.46,2553.92 h60
  text "ENEPIG" at 13731,2550.64 h60
  text "SURFACE FINISH:" at 11332.46,2549.64 h60
  text "X" at 12206.51,2549.64 h60
  text "IMM. TIN/SILVER OR EQUIV" at 11662,2392.64 h60
  text "OTHER" at 13093.46,2392.64 h60
  text "ARRAY/PANEL:" at 11332.46,2213.64 h60
  text "CUT AND TRIM PER MECH LAYER 1" at 12393.46,2209.35 h60
  text "N.C. ROUTE" at 12393.46,2057.64 h60
  text "X" at 13072.46,2057.64 h60
  text "V. SCORE" at 13259.46,2057.64 h60
  text "CERTIFICATION:" at 11332.46,1920.64 h60
  text "MATERIALS AND WORKMANSHIP FOR ALL PCBS" at 12057.46,1920.64 h60
  text "TO MEET OR EXCEED THE REQUIREMENTS OF:" at 12057.46,1822.64 h60
  text "X" at 11683.96,1686.13 h60
  text "ANSI IPC-A-600F CLASS ->" at 11822.96,1686.13 h60
  text "X" at 13462.02,1686.13 h60
  text "2" at 13580.96,1686.14 h60
  text "1" at 13265.96,1684.64 h60
  text "3" at 13934.96,1684.64 h60
  text "X" at 11686.02,1526.64 h60
  text "UL 94V-0" at 11822.96,1526.64 h60
  text "X" at 12498.02,1526.64 h60
  text "RoHS" at 12634.96,1526.64 h60
  text "OTHER" at 13279.36,1526.64 h60
  text "PER ORDER" at 13676.42,1526.64 h60
  text "ADDITIONAL REQUIREMENTS:" at 11332.46,1385.64 h60
  text "MICROSECTION:" at 11407.23,1270.64 h60
  text "YES" at 12312.96,1270.64 h60
  text "REQUIRED" at 13174.46,1114.49 h60
  text "BARE BOARD ELEC. TEST:" at 11407.23,1111.64 h60
  text "NONE" at 12712.96,1111.64 h60
  text "X" at 13047.46,1111.64 h60
  text "PER ORDER" at 13766.46,1111.64 h60
  text "MANUFACTURER'S UL:" at 11407.23,954.64 h60
  text "RAIL" at 12572.96,950.35 h60
  text "METAL" at 13064.77,950.35 h60
  text "X" at 13440,950 h60
  text "SILK" at 13576.46,950.35 h60
  text ".Layer_Name" at 577,-858.49 h60
M11 Gerber Information:
  lines w10: -292,-930.17 6308,-930.17 ; -292,-726.83 6310,-726.83 ; -292,-523.5 -292,-1133.5 3713,-1133.5 6310,-1133.5 6310,-523.5 -291.5,-523.5 -291.5,-1133.5 1284,-1133.5 ; 2173,-1133.5 2173,-523.5 ; 3440,-726.83 3440,-523.5 ; 4280,-726.83 4280,-523.5 ; 4902,-1140 4902,-937.17
  text "ALL ARTWORK VIEWED FROM TOP SIDE" at -228.5,-655.67 h60
  text "BOARD #:" at 2248,-655.67 h60
  text ".PRJ_Number" at 2793.5,-655.67 h60
  text "REV:" at 3638,-655.67 h60
  text ".PCB_Rev" at 3929.5,-655.67 h60
  text "SVN REV:" at 4476,-655.67 h60
  text ".VersionControl_RevNumber" at 4982,-655.67 h60
  text "LAYER NAME =" at -228.5,-858.49 h60
  text "TID #:" at 2248,-859 h60
  text ".TID" at 2793.5,-859 h60
  text "PLOT NAME =" at -228.5,-1064.34 h60
  text ".plot_File_Name" at 577,-1064.34 h60
  text "GENERATED    :" at 2250,-1064.34 h60
  text ".Print_Date" at 3119.5,-1064.34 h60
  text ".Print_Time" at 3848.5,-1064.34 h60
  text "TEXAS INSTRUMENTS" at 5113,-1064.34 h60
M12 Stackup:
  drawing of 295 lines, arcs and shapes, not listed
  text "Layer" at 9290,7820 h60
  text "Name" at 9699.91,7820 h60
  text "Material" at 11109.5,7820 h60
  text "Thickness" at 11969.27,7820 h60
  text "Constant" at 12619.1,7820 h60
  text "Board Layer Stack" at 13188.97,7820 h60
  text "1" at 9290,7700 h60
  text "Top Overlay" at 9699.91,7700 h60
  text "2" at 9290,7580 h60
  text "Top Solder" at 9699.91,7580 h60
  text "Solder Resist" at 11109.5,7580 h60
  text "0.40mil" at 11969.27,7580 h60
  text "3.5" at 12619.1,7580 h60
  text "3" at 9290,7460 h60
  text "Layer 1 - Top Layer" at 9699.91,7460 h60
  text "Copper" at 11109.5,7460 h60
  text "1.40mil" at 11969.27,7460 h60
  text "4" at 9290,7340 h60
  text "Dielectric 1" at 9699.91,7340 h60
  text "370HR" at 11109.5,7340 h60
  text "18.60mil" at 11969.27,7340 h60
  text "4.2" at 12619.1,7340 h60
  text "5" at 9290,7220 h60
  text "Layer 2 - GND" at 9699.91,7220 h60
  text "Copper" at 11109.5,7220 h60
  text "1.42mil" at 11969.27,7220 h60
  text "6" at 9290,7100 h60
  text "Dielectric 2" at 9699.91,7100 h60
  text "370HR" at 11109.5,7100 h60
  text "18.60mil" at 11969.27,7100 h60
  text "4.8" at 12619.1,7100 h60
  text "7" at 9290,6980 h60
  text "Layer 3 - PWR" at 9699.91,6980 h60
  text "Copper" at 11109.5,6980 h60
  text "1.42mil" at 11969.27,6980 h60
  text "8" at 9290,6860 h60
  text "Dielectric 3" at 9699.91,6860 h60
  text "370HR" at 11109.5,6860 h60
  text "18.60mil" at 11969.27,6860 h60
  text "4.2" at 12619.1,6860 h60
  text "9" at 9290,6740 h60
  text "Layer 4 - Bottom Layer" at 9699.91,6740 h60
  text "Copper" at 11109.5,6740 h60
  text "1.40mil" at 11969.27,6740 h60
  text "10" at 9290,6620 h60
  text "Bottom Solder" at 9699.91,6620 h60
  text "Solder Resist" at 11109.5,6620 h60
  text "0.40mil" at 11969.27,6620 h60
  text "3.5" at 12619.1,6620 h60
  text "11" at 9290,6500 h60
  text "Bottom Overlay" at 9699.91,6500 h60
  text ".Layer_Name" at 577,-858.49 h60
M13 Component Bodies Top:
  text ".Layer_Name" at 577,-858.49 h60
M14 Component Bodies Bottom:
  text ".Layer_Name" at 577,-858.49 h60
M15 Courtyards Top:
  text ".Layer_Name" at 577,-858.49 h60
M16 Courtyards Bottom:
  text ".Layer_Name" at 577,-858.49 h60
Drill Drawing:
  circle w1: c4517.72,2932.4 r24.89
  lines w1: 4492.83,2160.92 4542.6,2160.92 4542.6,2210.69 4492.83,2210.69 4492.83,2160.92 ; 4492.83,2322.68 4505.27,2322.68 4505.27,2310.24 4530.16,2310.24 4530.16,2322.68 4542.6,2322.68 4542.6,2347.57 4530.16,2347.57 4530.16,2360.01 4505.27,2360.01 4505.27,2347.57 4492.83,2347.57 4492.83,2322.68 ; 4492.83,2459.56 4517.72,2472 4542.6,2459.56 4530.16,2484.44 4542.6,2509.33 4517.72,2496.89 4492.83,2509.33 4505.27,2484.44 4492.83,2459.56 ; 4492.83,2658.65 4542.6,2658.65 4517.72,2608.88 4492.83,2658.65 ; 4492.83,2758.2 4542.6,2758.2 4542.6,2807.97 4492.83,2807.97 4492.83,2758.2 ; 4492.83,3081.72 4517.72,3056.84 4542.6,3081.72 4517.72,3106.61 4492.83,3081.72 ; 4492.83,3206.16 4492.83,3218.6 4505.27,3231.04 4492.83,3243.49 4492.83,3255.93 4505.27,3255.93 4517.72,3243.49 4530.16,3255.93 4542.6,3255.93 4542.6,3243.49 4530.16,3231.04 4542.6,3218.6 4542.6,3206.16 4530.16,3206.16 4517.72,3218.6 4505.27,3206.16 4492.83,3206.16 ; 4502.78,2768.15 4532.65,2768.15 4532.65,2798.01 4502.78,2798.01 4502.78,2768.15
  lines w12: 4425,2116.12 6543.02,2116.12 ; 4425,3310.68 6543.02,3310.68 ; 4795.36,1966.8 4795.36,3460 ; 5152.36,1966.8 5152.36,3460 ; 5813.93,1966.8 5813.93,3460 ; 6098.07,1966.8 6098.07,3460 ; 4425,1966.8 6543.02,1966.8 6543.02,3460 4425,3460 4425,1966.8
  text "Symbol" at 4514.59,3355.48 h72
  text "Quantity" at 4840.16,3355.48 h72
  text "Finished Hole Size" at 5197.16,3355.48 h72
  text "Plated" at 5858.72,3355.48 h72
  text "Hole Type" at 6142.86,3355.48 h72
  text "1" at 4840.16,3206.16 h60
  text "62.99mil (1.600mm)" at 5197.16,3206.16 h60
  text "NPTH" at 5858.72,3206.16 h60
  text "Round" at 6142.86,3206.16 h60
  text "1" at 4840.16,3056.84 h60
  text "70.87mil (1.800mm)" at 5197.16,3056.84 h60
  text "NPTH" at 5858.72,3056.84 h60
  text "Round" at 6142.86,3056.84 h60
  text "23" at 4840.16,2907.52 h60
  text "7.87mil (0.200mm)" at 5197.16,2907.52 h60
  text "PTH" at 5858.72,2907.52 h60
  text "Round" at 6142.86,2907.52 h60
  text "305" at 4840.16,2758.2 h60
  text "10.00mil (0.254mm)" at 5197.16,2758.2 h60
  text "PTH" at 5858.72,2758.2 h60
  text "Round" at 6142.86,2758.2 h60
  text "17" at 4840.16,2608.88 h60
  text "33.46mil (0.850mm)" at 5197.16,2608.88 h60
  text "PTH" at 5858.72,2608.88 h60
  text "Round" at 6142.86,2608.88 h60
  text "26" at 4840.16,2459.56 h60
  text "40.00mil (1.016mm)" at 5197.16,2459.56 h60
  text "PTH" at 5858.72,2459.56 h60
  text "Round" at 6142.86,2459.56 h60
  text "2" at 4840.16,2310.24 h60
  text "51.18mil (1.300mm)" at 5197.16,2310.24 h60
  text "PTH" at 5858.72,2310.24 h60
  text "Round" at 6142.86,2310.24 h60
  text "4" at 4840.16,2160.92 h60
  text "125.98mil (3.200mm)" at 5197.16,2160.92 h60
  text "PTH" at 5858.72,2160.92 h60
  text "Round" at 6142.86,2160.92 h60
  text "379 Total" at 4840.16,2011.6 h60
  text ".Layer_Name" at 577,-858.49 h60

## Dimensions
0,-400 to 1000,-400 on M2 Board Dimensions
0,0 to 0,3450 on M2 Board Dimensions
0,0 to 4000,0 on M2 Board Dimensions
